// Mitsubishi GX Works2 project: 18.用计数器做定时提醒   PLC: FX3U/FX3UC

PROGRAM MAIN
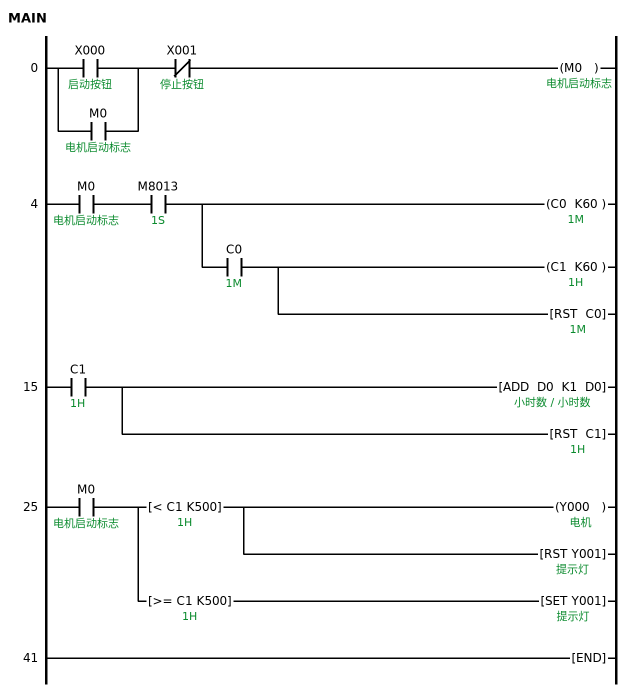
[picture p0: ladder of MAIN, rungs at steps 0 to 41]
0     LD      X000  ; 启动按钮
      OR      M0  ; 电机启动标志
      ANI     X001  ; 停止按钮
      OUT     M0  ; 电机启动标志
4     LD      M0  ; 电机启动标志
      AND     M8013  ; 1S
      OUT     C0 K60  ; 1M
      AND     C0  ; 1M
      OUT     C1 K60  ; 1H
      RST     C0  ; 1M
15    LD      C1  ; 1H
      ADD     D0 K1 D0  ; 小时数
      RST     C1  ; 1H
25    LD      M0  ; 电机启动标志
      MPS
      AND<    C1 K500  ; 1H
      OUT     Y000  ; 电机
      RST     Y001  ; 提示灯
      MPP
      AND>=   C1 K500  ; 1H
      SET     Y001  ; 提示灯
41    END
END_PROGRAM

// device comments not shown above
T0  ; 计时器
